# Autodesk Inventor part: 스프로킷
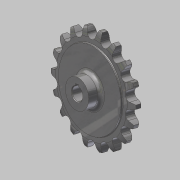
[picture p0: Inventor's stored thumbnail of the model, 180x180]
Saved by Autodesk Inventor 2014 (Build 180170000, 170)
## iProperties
Created: 2016-03
Part Number: 스프로킷
Material: 강철, 탄소
Document SubType Name: Modeling
Designer: mduedu
Density: 7.87 g/cm^3
Mass: 301.857 g
Surface Area: 120.622 cm^2
Volume: 38.3554 cm^3
Appearance: 반광택
Author: mduedu
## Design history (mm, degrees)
sketch "스케치1"
  geometry: L1 (0, 5)-(29.5, 5); L2 (29.5, 5)-(29.5, 4.1); L3 (30, 3.6)-(33.625, 3.6); L4 (40, 2)-(40, 0); L5 (40, 0)-(0, 0); L6 (0, 0)-(0, 5); L7 (0, -5)-(29.5, -5); L8 (29.5, -5)-(29.5, -4.1); L9 (30, -3.6)-(33.625, -3.6); L10 (40, -2)-(40, 0); L11 (0, 0)-(0, -5); A1 r 13.5 centre (33.625, -9.9) between (40, 2) and (33.625, 3.6); A2 r 13.5 centre (33.625, 9.9) between (33.625, -3.6) and (40, -2); A3 r 0.5 centre (30, 4.1) between (29.5, 4.1) and (30, 3.6); A4 r 0.5 centre (30, -4.1) between (30, -3.6) and (29.5, -4.1); 2 further points
  constraints: 22 end point, 8 point on circle, 6 symmetric about line, 5 tangent, 4 centre point, 4 parallel, 4 point on line, 1 equal radius, 1 horizontal, 1 perpendicular, 1 other
  dimensions: "d0" = 80 diameter of L4 L6; "d2" = 59 diameter of L2 L6; "d3" = 1.6 vertical distance of L4.start L3.end; "d4" = 3.6 distance from line of L4.end L3; "d5" = 5 distance between parallel lines of L5 L1; "d6" = 13.5 radius of A1; "d15" = 0.5 radius of A3
revolve "회전1" sketch "스케치1" stored, may be unused: angle "d7" = 90 deg
sketch "스케치2" dims "d8" = 65.2, "d11" = 80
  geometry: L1 (0, 0)-(0, 32.6); A1 r 36.57 centre (0, 0) between (-16.231, 32.771) and (0, 36.57); A2 r 3.97 centre (0, 36.57) between (-3.866, 35.665) and (0, 32.6); A3 r 12.7 centre (-16.231, 32.771) between (-3.866, 35.665) and (-5.534, 39.615); A4 r 12.7 centre (16.231, 32.771) between (5.534, 39.615) and (3.866, 35.665); A5 r 3.97 centre (0, 36.57) between (0, 32.6) and (3.866, 35.665); A6 r 40 centre (0, 0) between (5.534, 39.615) and (-5.534, 39.615); 2 further points
  constraints: 12 point on circle, 6 centre point, 4 coincident, 3 symmetric about line, 2 end point, 1 point on line, 1 tangent, 1 vertical, 1 vertical alignment, 7 other
  dimensions: "d10" = 73.14 diameter of A1; "d12" = 12.7 radius of A3
extrude "돌출1" cut sketch "스케치2" stored distance "d13" = 10; taper "d14" = 0 deg
sketch "스케치3"
  geometry: C1 r 11 at (0, 0); 1 further point
  constraints: 1 centre point, 1 coincident
  dimensions: "d19" = 22 diameter of C1
extrude "돌출2" join sketch "스케치3" distance "d20" = 10; taper "d21" = 0 deg
fillet "모깎기1" dims "d22" = 3
sketch "스케치4"
  geometry: L1 (-1.5, 0)-(1.5, 0); L2 (1.5, 0)-(1.5, 6.4); L3 (1.5, 6.4)-(-1.5, 6.4); L4 (-1.5, 6.4)-(-1.5, 0); C1 r 5 at (0, 0); 2 further points
  constraints: 8 end point, 2 coincident, 2 parallel, 1 centre point, 1 horizontal, 1 midpoint, 1 perpendicular
  dimensions: "d23" = 10 diameter of C1; "d25" = 3 distance of L2.end L3.end; "d26" = 6.4 distance of L1.end L2.end
extrude "돌출3" cut sketch "스케치4" stored distance "d27" = 8; taper "d28" = 0 deg
chamfer "모따기1" distance "d29" = 0.5; stored, may be unused: second distance "d30" = 2, angle "d31" = 45 deg
sketch "스케치5" dims "d33" = 50
  geometry: C1 r 1 at (0, 25); 2 further points
  constraints: 2 vertical alignment, 1 centre point, 1 coincident, 2 other
  dimensions: "d32" = 2 diameter of C1
extrude "돌출4" join sketch "스케치5" distance "d34" = 0.5; taper "d35" = 0 deg
node "솔리드1"
pattern_circular "원형 패턴1" dims angle "d17" = 360 deg
